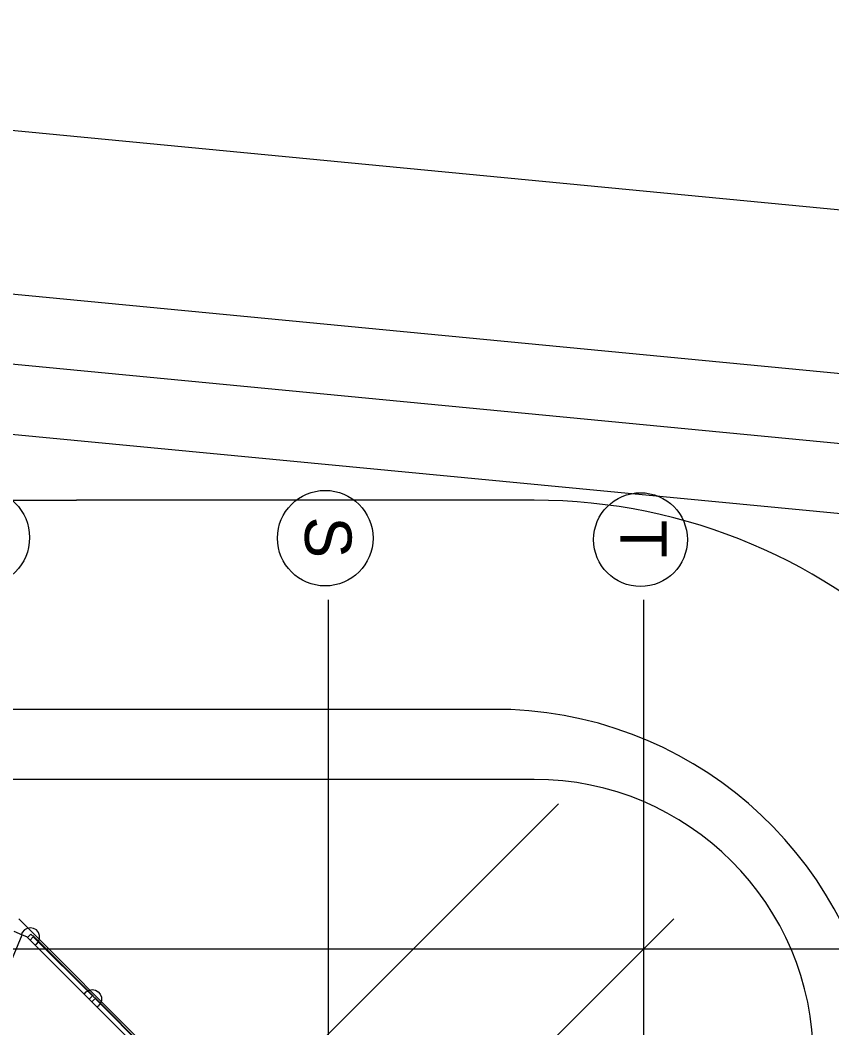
# Model space of a CAD drawing. Extents: x -264165 to -263575, y -1242333 to -1242036.
# Drawn here: x -263808.94 to -263791.5, y -1242089.65 to -1242067.99 of the extents above; entities that cross this region are included whole.
import ezdxf

# ---------------------------------------------------------------- set-up
doc = ezdxf.new("R2010")
doc.units = 0
doc.layers.add('KFA_HESCON_OSI_STAVBY', color=7, linetype='Continuous')
doc.layers.add('KFA_SITUACIA_DRS_VYTYCOVAK_SEDA', color=7, linetype='Continuous')

msp = doc.modelspace()

# ---------------------------------------------------------------- linework, layer by layer
at = {"layer": 'KFA_HESCON_OSI_STAVBY'}
for p, q in [((-263802.318, -1242080.447), (-263802.318, -1242080.447)), ((-263802.318, -1242080.447), (-263802.318, -1242248.737)), ((-263795.543, -1242080.447), (-263795.543, -1242080.447)), ((-263795.543, -1242080.447), (-263795.543, -1242248.737)), ((-263797.368, -1242084.832), (-263815.42, -1242102.885)), ((-263797.368, -1242084.832), (-263797.368, -1242084.832)), ((-263819.468, -1242111.882), (-263794.893, -1242087.307)), ((-263787.486, -1242087.957), (-263921.823, -1242087.957))]:
    msp.add_line(p, q, dxfattribs=at)
for centre, radius in [((-263809.783, -1242079.111), 1.047), ((-263802.383, -1242079.124), 1.027), ((-263795.608, -1242079.155), 1.008)]:
    msp.add_circle(centre, radius, dxfattribs=at)
at = {"layer": 'KFA_SITUACIA_DRS_VYTYCOVAK_SEDA'}
for p, q in [((-263765.318, -1242074.565), (-263863.949, -1242065.106)), ((-263765.364, -1242078.076), (-263864.283, -1242068.59)), ((-263766.58, -1242079.467), (-263864.426, -1242070.084)), ((-263765.366, -1242081.09), (-263864.57, -1242071.577)), ((-263766.58, -1242080.973), (-263864.546, -1242071.579)), ((-263918.093, -1242078.308), (-263807.725, -1242078.308)), ((-263797.893, -1242078.308), (-263807.725, -1242078.308)), ((-263808.225, -1242082.808), (-263916.593, -1242082.808)), ((-263798.393, -1242082.808), (-263808.225, -1242082.808)), ((-263807.725, -1242084.308), (-263851.968, -1242084.308)), ((-263797.893, -1242084.308), (-263807.725, -1242084.308)), ((-263808.968, -1242087.307), (-263794.893, -1242101.382)), ((-263809.186, -1242088.357), (-263808.893, -1242087.649)), ((-263809.186, -1242088.357), (-263808.893, -1242087.649)), ((-263809.077, -1242087.572), (-263808.893, -1242087.649)), ((-263809.077, -1242087.572), (-263808.893, -1242087.649)), ((-263808.892, -1242087.598), (-263808.908, -1242087.642)), ((-263808.892, -1242087.598), (-263808.908, -1242087.642)), ((-263808.893, -1242087.649), (-263808.8, -1242087.687)), ((-263808.893, -1242087.649), (-263808.8, -1242087.687)), ((-263808.847, -1242087.544), (-263808.892, -1242087.598)), ((-263808.847, -1242087.544), (-263808.892, -1242087.598)), ((-263808.787, -1242087.51), (-263808.847, -1242087.544)), ((-263808.787, -1242087.51), (-263808.847, -1242087.544)), ((-263808.719, -1242087.498), (-263808.787, -1242087.51)), ((-263808.719, -1242087.498), (-263808.787, -1242087.51)), ((-263808.783, -1242087.705), (-263808.712, -1242087.634)), ((-263808.783, -1242087.705), (-263808.712, -1242087.634)), ((-263808.65, -1242087.51), (-263808.719, -1242087.498)), ((-263808.65, -1242087.51), (-263808.719, -1242087.498)), ((-263808.712, -1242087.634), (-263808.676, -1242087.67)), ((-263808.712, -1242087.634), (-263808.676, -1242087.67)), ((-263808.59, -1242087.544), (-263808.65, -1242087.51)), ((-263808.59, -1242087.544), (-263808.65, -1242087.51)), ((-263808.546, -1242087.598), (-263808.59, -1242087.544)), ((-263808.546, -1242087.598), (-263808.59, -1242087.544)), ((-263808.522, -1242087.663), (-263808.546, -1242087.598)), ((-263808.522, -1242087.663), (-263808.546, -1242087.598)), ((-263808.8, -1242087.687), (-263804.511, -1242091.976)), ((-263808.8, -1242087.687), (-263804.511, -1242091.976)), ((-263804.511, -1242091.976), (-263808.8, -1242087.687)), ((-263804.511, -1242091.976), (-263808.8, -1242087.687)), ((-263808.726, -1242087.761), (-263808.783, -1242087.705)), ((-263808.726, -1242087.761), (-263808.783, -1242087.705)), ((-263808.655, -1242087.69), (-263808.726, -1242087.761)), ((-263808.655, -1242087.69), (-263808.726, -1242087.761)), ((-263808.669, -1242087.663), (-263808.676, -1242087.67)), ((-263808.669, -1242087.663), (-263808.676, -1242087.67)), ((-263808.669, -1242087.663), (-263807.354, -1242088.977)), ((-263808.669, -1242087.663), (-263807.354, -1242088.977)), ((-263807.382, -1242088.963), (-263808.655, -1242087.69)), ((-263807.382, -1242088.963), (-263808.655, -1242087.69)), ((-263808.62, -1242087.868), (-263808.59, -1242087.851)), ((-263808.62, -1242087.868), (-263808.59, -1242087.851)), ((-263808.59, -1242087.851), (-263808.547, -1242087.799)), ((-263808.59, -1242087.851), (-263808.547, -1242087.799)), ((-263808.543, -1242087.789), (-263808.522, -1242087.732)), ((-263808.543, -1242087.789), (-263808.522, -1242087.732)), ((-263808.522, -1242087.732), (-263808.522, -1242087.663)), ((-263808.522, -1242087.732), (-263808.522, -1242087.663)), ((-263804.723, -1242091.764), (-263808.398, -1242088.089)), ((-263804.723, -1242091.764), (-263808.398, -1242088.089)), ((-263807.561, -1242088.926), (-263807.518, -1242088.874)), ((-263807.561, -1242088.926), (-263807.518, -1242088.874)), ((-263807.518, -1242088.874), (-263807.489, -1242088.857)), ((-263807.518, -1242088.874), (-263807.489, -1242088.857)), ((-263807.48, -1242088.852), (-263807.458, -1242088.839)), ((-263807.48, -1242088.852), (-263807.458, -1242088.839)), ((-263807.458, -1242088.839), (-263807.389, -1242088.827)), ((-263807.458, -1242088.839), (-263807.389, -1242088.827)), ((-263807.389, -1242088.827), (-263807.321, -1242088.839)), ((-263807.389, -1242088.827), (-263807.321, -1242088.839)), ((-263807.321, -1242088.839), (-263807.261, -1242088.874)), ((-263807.321, -1242088.839), (-263807.261, -1242088.874)), ((-263807.261, -1242088.874), (-263807.216, -1242088.927)), ((-263807.261, -1242088.874), (-263807.216, -1242088.927)), ((-263807.216, -1242088.927), (-263807.192, -1242088.992)), ((-263807.216, -1242088.927), (-263807.192, -1242088.992)), ((-263807.453, -1242089.034), (-263807.382, -1242088.963)), ((-263807.453, -1242089.034), (-263807.382, -1242088.963)), ((-263807.396, -1242089.091), (-263807.453, -1242089.034)), ((-263807.396, -1242089.091), (-263807.453, -1242089.034)), ((-263807.326, -1242089.02), (-263807.396, -1242089.091)), ((-263807.326, -1242089.02), (-263807.396, -1242089.091)), ((-263807.354, -1242088.977), (-263807.362, -1242088.984)), ((-263807.354, -1242088.977), (-263807.362, -1242088.984)), ((-263807.362, -1242088.984), (-263807.347, -1242088.999)), ((-263807.362, -1242088.984), (-263807.347, -1242088.999)), ((-263807.347, -1242088.999), (-263807.34, -1242088.992)), ((-263807.347, -1242088.999), (-263807.34, -1242088.992)), ((-263807.34, -1242088.992), (-263806.025, -1242090.307)), ((-263807.34, -1242088.992), (-263806.025, -1242090.307)), ((-263806.053, -1242090.293), (-263807.326, -1242089.02)), ((-263806.053, -1242090.293), (-263807.326, -1242089.02)), ((-263807.217, -1242089.128), (-263807.261, -1242089.18)), ((-263807.217, -1242089.128), (-263807.261, -1242089.18)), ((-263807.192, -1242089.062), (-263807.213, -1242089.118)), ((-263807.192, -1242089.062), (-263807.213, -1242089.118)), ((-263807.192, -1242088.992), (-263807.192, -1242089.062)), ((-263807.192, -1242088.992), (-263807.192, -1242089.062)), ((-263807.261, -1242089.18), (-263807.29, -1242089.197)), ((-263807.261, -1242089.18), (-263807.29, -1242089.197))]:
    msp.add_line(p, q, dxfattribs=at)
for centre, radius, start, end in [((-263797.893, -1242090.308), 12, 0, 90), ((-263798.744, -1242091.156), 8.355, 5.8252, 87.5906), ((-263797.893, -1242090.308), 6, 0, 90)]:
    msp.add_arc(centre, radius, start, end, dxfattribs=at)

# ---------------------------------------------------------------- texts
at = {"layer": 'KFA_HESCON_OSI_STAVBY'}
for s, p in [('S', (-263802.818, -1242078.659)), ('T', (-263796.043, -1242078.729))]:
    msp.add_text(s, height=1, rotation=270, dxfattribs=at).set_placement(p)

doc.saveas('drawing.dxf')
